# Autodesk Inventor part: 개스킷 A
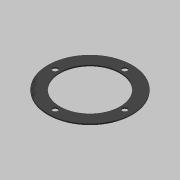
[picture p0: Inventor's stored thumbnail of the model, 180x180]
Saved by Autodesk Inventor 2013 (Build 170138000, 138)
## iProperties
Created: 2019-02
Part Number: 개스킷 A
Material: 고무
Document SubType Name: Modeling
Designer: mduedu
Density: 0.93 g/cm^3
Mass: 1.69384 g
Surface Area: 40.7622 cm^2
Volume: 1.82134 cm^3
Author: mduedu
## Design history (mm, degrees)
sketch "스케치1"
  geometry: C1 r 35 at (0, 0); C2 r 25 at (0, 0); 1 further point
  constraints: 2 centre point, 2 coincident
  dimensions: "d0" = 70 diameter of C1; "d1" = 50 diameter of C2
extrude "돌출1" new body sketch "스케치1" distance "d2" = 1; taper "d3" = 0 deg
sketch "스케치2" dims "d4" = 58
  geometry: 3 further points
  constraints: 2 vertical alignment, 1 coincident, 2 other
hole "구멍1" sketch "스케치2" at (0, 29) diameter "d5" = 4.5; stored, may be unused: countersink angle "d9" = 90 deg, drill point angle "d11" = 118 deg; dims "d6" = 6, "d7" = 4, "d8" = 2, "d10" = 8
node "솔리드1"
pattern_circular "원형 패턴1" dims angle "d13" = 360 deg
